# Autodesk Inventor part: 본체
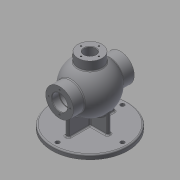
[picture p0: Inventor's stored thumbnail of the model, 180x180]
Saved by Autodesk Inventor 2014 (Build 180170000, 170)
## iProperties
Created: 2020-08
Part Number: 본체
Material: Generic
Document SubType Name: Modeling
Designer: kh
Density: 1 g/cm^3
Appearance: Default
Author: kh
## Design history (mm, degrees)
sketch "Sketch1"
  geometry: C1 r 85 at (0, 0); 1 further point
  constraints: 1 centre point, 1 coincident
  dimensions: "d0" = 170 diameter of C1
extrude "Extrusion1" new body sketch "Sketch1" distance "d1" = 10; taper "d2" = 0 deg
sketch "Sketch2"
  geometry: L1 (-87.595, 85)-(79.188, 85); L2 (-68, 102.5)-(-52, 102.5); L3 (-52, 102.5)-(-52, 103.5); L4 (-52, 103.5)-(-50.25, 103.5); L5 (-50.25, 103.5)-(-50.25, 102.5); L6 (-50.25, 102.5)-(-39.278, 102.5); L7 (68, 102.5)-(39.278, 102.5); L8 (-68, 102.5)-(-68, 116); L9 (-68, 116)-(-42.988, 116); L10 (68, 102.5)-(68, 116); L11 (68, 116)-(42.988, 116); L12 (0, 0)-(0, 38.889); L13 (-85, 0)-(85, 0) reference; A1 r 43 centre (0, 85) between (39.278, 102.5) and (-39.278, 102.5); A2 r 53 centre (0, 85) between (42.988, 116) and (-42.988, 116)
  constraints: 24 end point, 6 perpendicular, 4 point on circle, 3 parallel, 2 centre point, 2 collinear, 2 point on line, 1 horizontal, 1 other
  dimensions: "d3" = 35 diameter of L2 L1; "d4" = 37 diameter of L4 L1; "d5" = 35 diameter of L6 L1; "d6" = 35 diameter of L7 L1; "d7" = 62 diameter of L11 L1; "d8" = 62 diameter of L9 L1; "d9" = 53 radius of A2; "d10" = 43 radius of A1; "d11" = 85 distance from line of L13 L1.end; "d12" = 136 distance between parallel lines of L10 L8; "d13" = 1.75 distance of L3.end L4.end; "d14" = 16 distance of L2.start L2.end
revolve "Revolution1" sketch "Sketch2" stored, may be unused: angle "d15" = 90 deg
sketch "Sketch3"
  geometry: L1 (-43, -4)-(43, -4); L2 (43, -4)-(43, 4); L3 (43, 4)-(-43, 4); L4 (-43, 4)-(-43, -4); L5 (-43, -4)-(43, 4); L6 (43, -4)-(-43, 4); L7 (-4, -52)-(4, -52); L8 (4, -52)-(4, 52); L9 (4, 52)-(-4, 52); L10 (-4, 52)-(-4, -52); L11 (-4, -52)-(4, 52); L12 (4, -52)-(-4, 52); 1 further point
  constraints: 24 end point, 4 midpoint, 4 parallel, 2 horizontal, 2 perpendicular
  dimensions: "d16" = 86 distance of L2.end L3.end; "d17" = 8 distance of L1.end L2.end; "d18" = 8 distance of L8.end L9.end; "d19" = 104 distance of L7.end L8.end
extrude "Extrusion2" join sketch "Sketch3" stored distance "d20" = 10; taper "d21" = 0 deg
workplane "Work Plane1"
sketch "Sketch4"
  geometry: C1 r 27 at (0, 0); 1 further point
  constraints: 1 centre point, 1 coincident
  dimensions: "d23" = 54 diameter of C1
extrude "Extrusion3" join sketch "Sketch4" stored distance "d24" = 10; taper "d25" = 0 deg
hole "Hole1" diameter "d28" = 26; stored, may be unused: countersink angle "d32" = 90 deg, drill point angle "d34" = 118 deg; dims "d26" = 10, "d27" = 10, "d29" = 6, "d30" = 4, "d31" = 2, "d33" = 8
workplane "Work Plane2"
chamfer "Chamfer1" distance "d39" = 1; stored, may be unused: second distance "d40" = 2, angle "d41" = 45 deg
fillet "Fillet1" dims "d42" = 3
fillet "Fillet2" dims "d43" = 3
sketch "Sketch7" dims "d44" = 145
  geometry: L1 (0, 0)-(0, 72.5); 2 further points
  constraints: 2 coincident, 2 end point, 1 vertical, 1 vertical alignment, 2 other
hole "Hole2" sketch "Sketch7" at (0, 72.5) diameter "d45" = 9; stored, may be unused: countersink angle "d49" = 90 deg, drill point angle "d51" = 118 deg; dims "d46" = 6, "d47" = 4, "d48" = 2, "d50" = 8
pattern_circular "Circular Pattern1" dims angle "d53" = 360 deg
fillet "Fillet3" dims "d55" = 3
sketch "Sketch8" dims "d56" = 48
  geometry: L1 (0, 0)-(0, 24); C1 r 31 at (0, 0) reference; 2 further points
  constraints: 2 coincident, 2 end point, 1 vertical, 1 vertical alignment, 2 other
hole "Hole3" sketch "Sketch8" at (0, 24) diameter "d57" = 3.242; stored, may be unused: countersink angle "d61" = 90 deg, drill point angle "d63" = 118 deg; dims "d58" = 12, "d59" = 4, "d60" = 2, "d62" = 15
pattern_circular "Circular Pattern2" dims angle "d65" = 360 deg
sketch "Sketch9" dims "d67" = 48
  geometry: L1 (0, 0)-(0, -24); C1 r 31 at (0, 0) reference; 2 further points
  constraints: 2 coincident, 2 end point, 1 vertical, 1 vertical alignment, 2 other
hole "Hole4" sketch "Sketch9" at (0, -24) diameter "d68" = 3.242; stored, may be unused: countersink angle "d72" = 90 deg, drill point angle "d74" = 118 deg; dims "d69" = 12, "d70" = 4, "d71" = 2, "d73" = 15
pattern_circular "Circular Pattern3" dims angle "d76" = 360 deg
sketch "Sketch10" dims "d78" = 40
  geometry: L1 (0, 0)-(0, 20); C1 r 27 at (0, 0) reference; 2 further points
  constraints: 2 coincident, 2 end point, 1 vertical, 1 vertical alignment, 2 other
hole "Hole5" sketch "Sketch10" at (0, 20) diameter "d79" = 3.242; stored, may be unused: countersink angle "d83" = 90 deg, drill point angle "d85" = 118 deg; dims "d80" = 12, "d81" = 4, "d82" = 2, "d84" = 15
pattern_circular "Circular Pattern4" dims angle "d87" = 360 deg
fillet "Fillet4" dims "d89" = 3
workplane "Work Plane3"
sketch "Sketch11"
  geometry: L1 (-20.739, -5.998)-(20.739, -5.998); L2 (20.739, -5.998)-(20.739, -12.002); L3 (20.739, -12.002)-(-20.739, -12.002); L4 (-20.739, -12.002)-(-20.739, -5.998); L5 (-20.739, -5.998)-(20.739, -12.002); L6 (-27, 0)-(27, 0) reference; L7 (-27, 0)-(-27, -17.714) reference; 2 further points
  constraints: 2 end point, 1 midpoint, 2 other
  dimensions: "d90" = 9 distance from line of point (0, -9) L6; "d91" = 27 distance from line of L7 point (0, -9)
emboss "Emboss2" sketch "Sketch11" dims "d92" = 0.5, "d93" = 0
body "Solid1"
